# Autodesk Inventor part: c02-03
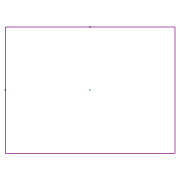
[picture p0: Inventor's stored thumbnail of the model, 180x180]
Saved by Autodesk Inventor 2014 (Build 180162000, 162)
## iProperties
Created: 2013-02
Part Number: c02-03
Material: Generic
Document SubType Name: Modeling
Designer: Thom Tremblay
Density: 1 g/cm^3
Appearance: Default
Author: Thom Tremblay
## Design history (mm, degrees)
sketch "Sketch1"
  geometry: L1 (12.952, -9.643)-(12.952, 9.643); L2 (12.952, 9.643)-(-12.952, 9.643); L3 (-12.952, 9.643)-(-12.952, -9.643); L4 (-12.952, -9.643)-(12.952, -9.643); 3 further points
  constraints: 8 end point, 2 midpoint, 1 horizontal, 1 horizontal alignment, 1 parallel, 1 perpendicular, 1 vertical, 1 vertical alignment, 1 other
